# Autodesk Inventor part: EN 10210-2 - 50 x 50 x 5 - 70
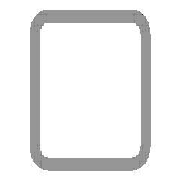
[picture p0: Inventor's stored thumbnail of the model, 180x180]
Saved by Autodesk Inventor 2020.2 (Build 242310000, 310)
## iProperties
IsCustomPart: 1
_CCFamilyMember: 16
_CCFamilyDisplayName: DIN EN 10210-2 (USAS B17.1 quadratisch) - Rohrleitung — In Klammern angegebene Größen wurden aufgehoben
_FrameMemberDoc: Frame Member File
_Version: 15.0.0
_GetPNFromCC: 1
Created: 2019-10
Part Number: EN 10210-2 - 50 x 50 x 5 - 70
Material: Stahl, weich
Description: Rohrleitung
Document SubType Name: Modeling
Standard: DIN
Designer: lutzd
Standard Revision: 2006-07
Standards Organization: DIN
Language: de-DE
Size Designation: 50 x 50 x 5
Categories: <MemberInstance><Categories><Category DisplayName="Profile" InternalName="089c4875-fa83-4c05-b084-43b9cc11f5ed" Mnemonic="GRDR"><CategoryParameter DisplayName="
Stock Number: 50 x 50 x 5
Mass: 479.81 g
Surface Area: 254.441 cm^2
Volume: 61.1222 cm^3
Density: 7.85 g/cm^3
Appearance: Semi-Polished(8)
G_L: 70,000 mm
G_W: 50,000 mm
G_H: 50,000 mm
Dimensions: 50x50x70 mm
Mass: 0,48 kg
DocNumber: ADSK-014289
Folder: .
+A634BCA0-4083-4782-9089-94E5061B7C3B+SCHNITTDETAIL1: Schnittwinkel 90,00 grd
VLT_Material: Stahl, weich
Title: Profil-Bauteil
Author: lutzd
Revision Number: -
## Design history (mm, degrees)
node "Startebene"
node "Endebene"
sketch "Skizze"
  geometry: L1 (-25, -17.5)-(-25, 17.5); L2 (-17.5, 25)-(17.5, 25); L3 (25, 17.5)-(25, -17.5); L4 (17.5, -25)-(-17.5, -25); L5 (-15, 20)-(15, 20); L6 (20, 15)-(20, -15); L7 (15, -20)-(-15, -20); L8 (-20, -15)-(-20, 15); L9 (0, 37.175)-(0, -37.175) reference; L10 (-37.175, 0)-(37.175, 0) reference; A1 r 7.5 centre (-17.5, -17.5) between (-25, -17.5) and (-17.5, -25); A2 r 7.5 centre (-17.5, 17.5) between (-17.5, 25) and (-25, 17.5); A3 r 7.5 centre (17.5, 17.5) between (25, 17.5) and (17.5, 25); A4 r 7.5 centre (17.5, -17.5) between (17.5, -25) and (25, -17.5); A5 r 5 centre (-15, -15) between (-20, -15) and (-15, -20); A6 r 5 centre (-15, 15) between (-15, 20) and (-20, 15); A7 r 5 centre (15, 15) between (20, 15) and (15, 20); A8 r 5 centre (15, -15) between (15, -20) and (20, -15)
  constraints: 16 end point, 16 point on circle, 16 tangent, 8 centre point, 6 equal radius, 4 parallel, 2 perpendicular, 2 other
  dimensions: "d7" = 7.5 radius of A1 (= G_IR); "d10" = 50 distance between parallel lines of L2 L4 (= G_H); "d11" = 50 distance between parallel lines of L1 L3 (= G_W); "d12" = 5 distance between parallel lines of L3 L6 (= G_T); "d15" = 25 distance between parallel lines of L2 L10 (= 0.5 x d10); "d16" = 25 distance between parallel lines of L9 L3 (= 0.5 x d11); "d19" = 5 radius of A5 (= G_T); "d20" = 5 distance between parallel lines of L4 L7 (= G_T)
extrude "Körper" new body sketch "Skizze" stored distance "d3" = 70 (= G_L); taper "d4" = 0 deg
node "Driven Length"
  sketch "Sketch3"
    geometry: L1 (0, 0)-(10, 0) reference
    constraints: 2 end point, 1 horizontal
  workplane "Work Plane3"
  sketch "Sketch4"
    geometry: L1 (-2, 25)-(12, 25) reference; L2 (-2, 95)-(12, 95) reference
    dimensions: "d18" = 70 distance between parallel lines of L1 L2 (derived)
workplane "Arbeitsebene4"
feature "Trennen1"
body "Solid1"
other parameters: "G_W" = 50 [user parameter; used in 1 equation term], "G_H" = 50 [user parameter; used in 1 equation term], "G_T" = 5 [user parameter; used in 3 equation terms], "G_IR" = 7.5 [user parameter; used in 1 equation term], "G_L" = 70 (= d18) [user parameter; used in 1 equation term], "G_OFFSET_START" = -25 [user parameter; used in 1 equation term], "G_OFFSET_END" = 0 [user parameter; used in 1 equation term], "d13" = 25 (= -G_OFFSET_START), "d14" = 95 (= G_OFFSET_END + B_L), "B_L" = 95 [user parameter; used in 1 equation term], "d17" = 90 deg
